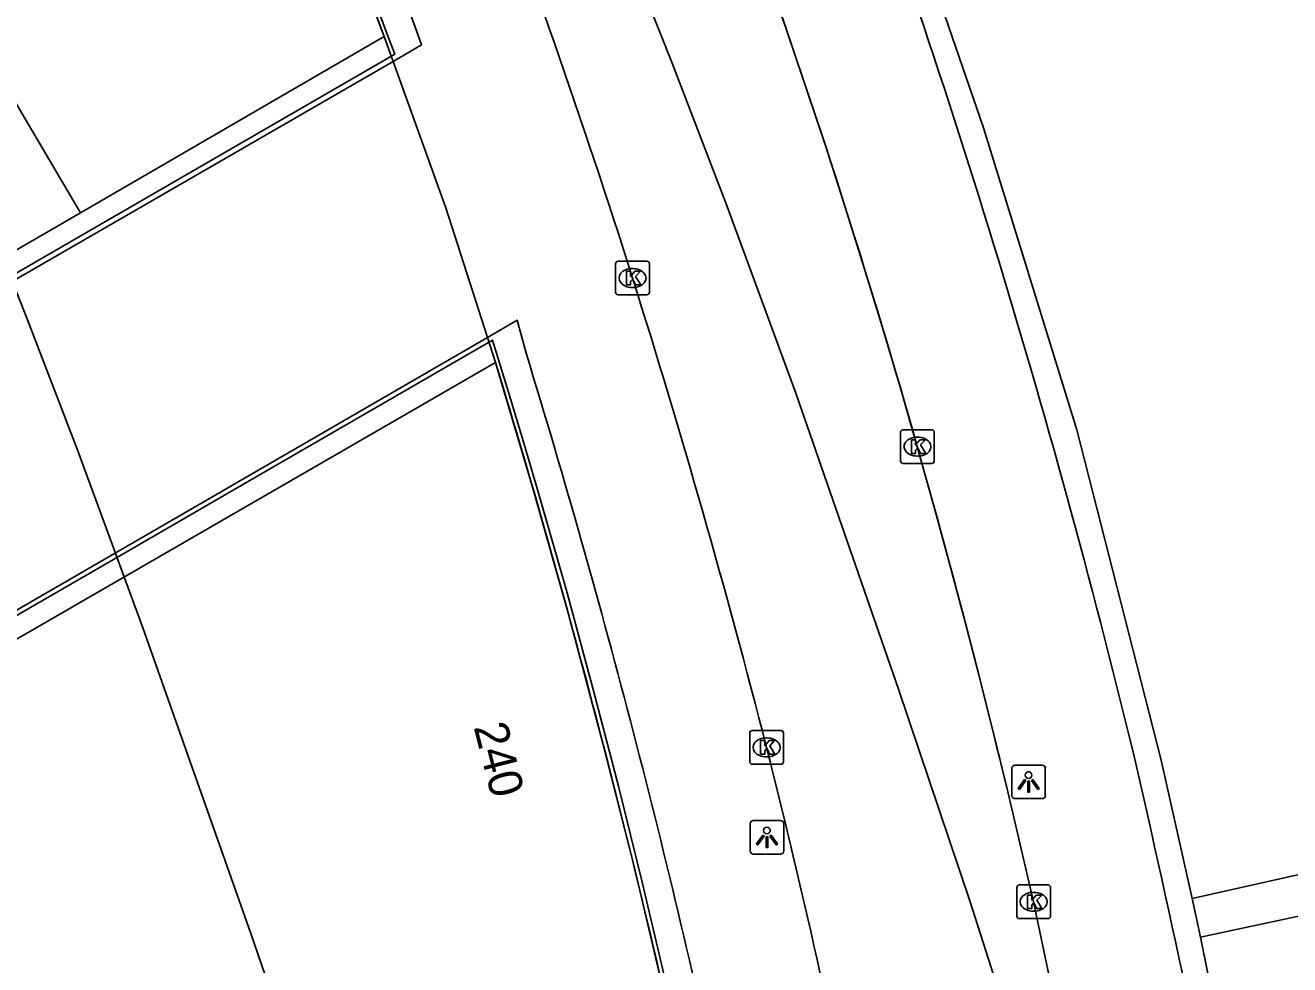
# Model space of a CAD drawing. Extents: x 155018 to 156648, y 383980 to 385733.
# Drawn here: x 156027.46 to 156064.97, y 384892.15 to 384920.02 of the extents above; entities that cross this region are included whole.
import ezdxf

# ---------------------------------------------------------------- set-up
doc = ezdxf.new("R2010")
doc.units = 0
for name, color, linetype in [('IMGEO_Dek', 7, 'Continuous'), ('IMGEO_Hek', 7, 'Continuous'), ('IMGEO_Kolk', 7, 'Continuous'), ('IMGEO_Lichtpunt', 7, 'Continuous'), ('IMGEO_Lijnafwatering', 7, 'Continuous'), ('IMGEO_OVBaan_gesloten', 7, 'Continuous'), ('IMGEO_Pand', 7, 'Continuous'), ('IMGEO_Pand_nummerreeks', 7, 'Continuous'), ('IMGEO_Pand_overbouw', 7, 'Continuous'), ('IMGEO_Parkeervlak_open', 7, 'Continuous'), ('IMGEO_Voetpad_gesloten', 7, 'Continuous'), ('IMGEO_Voetpad_op_trap', 7, 'Continuous'), ('IMGEO_Voetpad_open', 7, 'Continuous')]:
    doc.layers.add(name, color=color, linetype=linetype)

msp = doc.modelspace()

# ---------------------------------------------------------------- linework, layer by layer
at = {"layer": 'IMGEO_Dek'}
for points in [[(156068.116, 384859.746), (156067.041, 384867.895), (156066.062, 384873.898), (156064.757, 384880.912), (156062.331, 384892.966), (156062.08, 384894.114), (156061.157, 384898.221), (156058.656, 384908.023), (156055.886, 384916.978), (156051.936, 384928.479), (156048.02, 384938.183), (156047.794, 384938.745), (156047.79, 384938.857), (156046.063, 384942.673), (156044.343, 384946.44)], [(156027.709, 384944.118), (156028.763, 384941.944), (156029.793, 384939.759), (156030.8, 384937.563), (156031.783, 384935.357), (156032.743, 384933.14), (156033.68, 384930.916), (156034.6, 384928.685), (156035.502, 384926.446), (156036.386, 384924.2), (156037.253, 384921.947), (156038.102, 384919.688), (156039.932, 384914.604), (156041.169, 384910.762), (156041.409, 384910.017), (156042.517, 384906.291), (156043.573, 384902.55), (156044.577, 384898.794), (156045.528, 384895.025), (156046.426, 384891.242)]]:
    msp.add_lwpolyline(points, dxfattribs=at)
at = {"layer": 'IMGEO_Hek'}
for centre, radius, start, end in [((155804.106, 384836.212), 263.673, 13.559, 20.33305), ((155627.906, 384798.953), 443.726, 8.87476, 12.90185)]:
    msp.add_arc(centre, radius, start, end, dxfattribs=at)
at = {"layer": 'IMGEO_Kolk'}
for p, q in [((156044.973, 384912.099), (156044.973, 384912.951)), ((156045.048, 384913.025), (156045.9, 384913.025)), ((156045.461, 384912.805), (156045.486, 384912.805)), ((156045.974, 384912.951), (156045.974, 384912.099)), ((156045.484, 384912.245), (156045.459, 384912.245)), ((156045.9, 384912.025), (156045.048, 384912.025)), ((156053.428, 384907.096), (156053.428, 384907.948)), ((156053.503, 384908.022), (156054.355, 384908.022)), ((156054.429, 384907.948), (156054.429, 384907.096)), ((156053.916, 384907.802), (156053.941, 384907.802)), ((156053.939, 384907.242), (156053.914, 384907.242)), ((156054.355, 384907.022), (156053.503, 384907.022)), ((156048.953, 384898.173), (156048.953, 384899.025)), ((156049.028, 384899.099), (156049.88, 384899.099)), ((156049.954, 384899.025), (156049.954, 384898.173)), ((156049.441, 384898.879), (156049.466, 384898.879)), ((156049.464, 384898.319), (156049.439, 384898.319)), ((156049.88, 384898.099), (156049.028, 384898.099)), ((156056.878, 384893.592), (156056.878, 384894.444)), ((156056.953, 384894.518), (156057.805, 384894.518)), ((156057.879, 384894.444), (156057.879, 384893.592)), ((156057.366, 384894.298), (156057.391, 384894.298)), ((156057.389, 384893.738), (156057.364, 384893.738)), ((156057.805, 384893.518), (156056.953, 384893.518))]:
    msp.add_line(p, q, dxfattribs=at)
for points in [[(156044.973, 384912.099), (156044.973, 384912.951)], [(156045.048, 384913.025), (156045.9, 384913.025)], [(156045.974, 384912.951), (156045.974, 384912.099)], [(156045.294, 384912.725), (156045.417, 384912.725), (156045.417, 384912.574), (156045.547, 384912.725), (156045.711, 384912.725), (156045.565, 384912.574), (156045.718, 384912.325), (156045.566, 384912.325), (156045.481, 384912.489), (156045.417, 384912.422), (156045.417, 384912.325), (156045.294, 384912.325), (156045.294, 384912.725)], [(156045.9, 384912.025), (156045.048, 384912.025)], [(156053.428, 384907.096), (156053.428, 384907.948)], [(156053.503, 384908.022), (156054.355, 384908.022)], [(156054.429, 384907.948), (156054.429, 384907.096)], [(156053.749, 384907.722), (156053.872, 384907.722), (156053.872, 384907.571), (156054.002, 384907.722), (156054.166, 384907.722), (156054.02, 384907.571), (156054.173, 384907.322), (156054.021, 384907.322), (156053.936, 384907.486), (156053.872, 384907.419), (156053.872, 384907.322), (156053.749, 384907.322), (156053.749, 384907.722)], [(156054.355, 384907.022), (156053.503, 384907.022)], [(156048.953, 384898.173), (156048.953, 384899.025)], [(156049.028, 384899.099), (156049.88, 384899.099)], [(156049.954, 384899.025), (156049.954, 384898.173)], [(156049.274, 384898.799), (156049.397, 384898.799), (156049.397, 384898.648), (156049.527, 384898.799), (156049.691, 384898.799), (156049.545, 384898.648), (156049.698, 384898.399), (156049.546, 384898.399), (156049.461, 384898.563), (156049.397, 384898.496), (156049.397, 384898.399), (156049.274, 384898.399), (156049.274, 384898.799)], [(156049.88, 384898.099), (156049.028, 384898.099)], [(156056.878, 384893.592), (156056.878, 384894.444)], [(156056.953, 384894.518), (156057.805, 384894.518)], [(156057.879, 384894.444), (156057.879, 384893.592)], [(156057.199, 384894.218), (156057.322, 384894.218), (156057.322, 384894.067), (156057.452, 384894.218), (156057.616, 384894.218), (156057.47, 384894.067), (156057.623, 384893.818), (156057.471, 384893.818), (156057.386, 384893.982), (156057.322, 384893.915), (156057.322, 384893.818), (156057.199, 384893.818), (156057.199, 384894.218)], [(156057.805, 384893.518), (156056.953, 384893.518)]]:
    msp.add_lwpolyline(points, dxfattribs=at)
for centre, start, end in [((156045.05, 384912.949), 91.552, 178.448), ((156045.05, 384912.949), 91.552, 178.448), ((156045.898, 384912.949), 1.552, 88.448), ((156045.898, 384912.949), 1.552, 88.448), ((156045.05, 384912.101), 181.552, 268.448), ((156045.05, 384912.101), 181.552, 268.448), ((156045.898, 384912.101), 271.552, 358.448), ((156045.898, 384912.101), 271.552, 358.448), ((156053.505, 384907.946), 91.552, 178.448), ((156053.505, 384907.946), 91.552, 178.448), ((156054.353, 384907.946), 1.552, 88.448), ((156054.353, 384907.946), 1.552, 88.448), ((156053.505, 384907.098), 181.552, 268.448), ((156053.505, 384907.098), 181.552, 268.448), ((156054.353, 384907.098), 271.552, 358.448), ((156054.353, 384907.098), 271.552, 358.448), ((156049.03, 384899.023), 91.552, 178.448), ((156049.03, 384899.023), 91.552, 178.448), ((156049.878, 384899.023), 1.552, 88.448), ((156049.878, 384899.023), 1.552, 88.448), ((156049.03, 384898.175), 181.552, 268.448), ((156049.03, 384898.175), 181.552, 268.448), ((156049.878, 384898.175), 271.552, 358.448), ((156049.878, 384898.175), 271.552, 358.448), ((156056.955, 384894.442), 91.552, 178.448), ((156056.955, 384894.442), 91.552, 178.448), ((156057.803, 384894.442), 1.552, 88.448), ((156057.803, 384894.442), 1.552, 88.448), ((156056.955, 384893.594), 181.552, 268.448), ((156056.955, 384893.594), 181.552, 268.448), ((156057.803, 384893.594), 271.552, 358.448), ((156057.803, 384893.594), 271.552, 358.448)]:
    msp.add_arc(centre, 0.0765, start, end, dxfattribs=at)
for centre, major_axis, ratio, start_param, end_param in [((156045.46, 384912.525), (-0.387, 0.002), 0.722429, 4.712389, 7.853982), ((156045.485, 384912.525), (-0.39, 0.002), 0.717154, 1.570796, 4.712389), ((156053.915, 384907.522), (-0.387, 0.002), 0.722429, 4.712389, 7.853982), ((156053.94, 384907.522), (-0.39, 0.002), 0.717154, 1.570796, 4.712389), ((156049.44, 384898.599), (-0.387, 0.002), 0.722429, 4.712389, 7.853982), ((156049.465, 384898.599), (-0.39, 0.002), 0.717154, 1.570796, 4.712389), ((156057.365, 384894.018), (-0.387, 0.002), 0.722429, 4.712389, 7.853982), ((156057.39, 384894.018), (-0.39, 0.002), 0.717154, 1.570796, 4.712389)]:
    msp.add_ellipse(centre, major_axis=major_axis, ratio=ratio, start_param=start_param, end_param=end_param, dxfattribs=at)
at = {"layer": 'IMGEO_Lichtpunt'}
for p, q in [((156056.727, 384897.979), (156056.727, 384897.172)), ((156056.727, 384897.979), (156056.727, 384897.172)), ((156057.629, 384898.074), (156056.821, 384898.074)), ((156057.629, 384898.074), (156056.821, 384898.074)), ((156057.723, 384897.172), (156057.723, 384897.979)), ((156057.723, 384897.172), (156057.723, 384897.979)), ((156056.821, 384897.078), (156057.629, 384897.078)), ((156056.821, 384897.078), (156057.629, 384897.078)), ((156048.964, 384896.333), (156048.964, 384895.526)), ((156048.964, 384896.333), (156048.964, 384895.526)), ((156049.866, 384896.428), (156049.058, 384896.428)), ((156049.866, 384896.428), (156049.058, 384896.428)), ((156049.96, 384895.526), (156049.96, 384896.333)), ((156049.96, 384895.526), (156049.96, 384896.333)), ((156049.058, 384895.432), (156049.866, 384895.432)), ((156049.058, 384895.432), (156049.866, 384895.432))]:
    msp.add_line(p, q, dxfattribs=at)
for points in [[(156057.101, 384897.643), (156057.14, 384897.615), (156056.952, 384897.353), (156056.914, 384897.38), (156057.101, 384897.643)], [(156057.203, 384897.595), (156057.25, 384897.595), (156057.25, 384897.273), (156057.203, 384897.273), (156057.203, 384897.595)], [(156057.313, 384897.615), (156057.351, 384897.642), (156057.538, 384897.38), (156057.499, 384897.352), (156057.313, 384897.615)], [(156049.338, 384895.997), (156049.377, 384895.969), (156049.189, 384895.707), (156049.151, 384895.734), (156049.338, 384895.997)], [(156049.44, 384895.949), (156049.487, 384895.949), (156049.487, 384895.627), (156049.44, 384895.627), (156049.44, 384895.949)], [(156049.55, 384895.969), (156049.588, 384895.996), (156049.775, 384895.734), (156049.736, 384895.706), (156049.55, 384895.969)]]:
    msp.add_lwpolyline(points, dxfattribs=at)
for centre in [(156057.226, 384897.777), (156049.463, 384896.131)]:
    msp.add_circle(centre, 0.0994, dxfattribs=at)
for centre, start, end in [((156056.821, 384897.979), 90, 180), ((156056.821, 384897.979), 90, 180), ((156057.629, 384897.979), 0, 90), ((156057.629, 384897.979), 0, 90), ((156056.821, 384897.172), 180, 270), ((156056.821, 384897.172), 180, 270), ((156057.629, 384897.172), 270, 0), ((156057.629, 384897.172), 270, 360), ((156049.058, 384896.333), 90, 180), ((156049.058, 384896.333), 90, 180), ((156049.866, 384896.333), 0, 90), ((156049.866, 384896.333), 0, 90), ((156049.058, 384895.526), 180, 270), ((156049.058, 384895.526), 180, 270), ((156049.866, 384895.526), 270, 0), ((156049.866, 384895.526), 270, 360)]:
    msp.add_arc(centre, 0.0946, start, end, dxfattribs=at)
at = {"layer": 'IMGEO_Lijnafwatering'}
for points in [[(156027.883, 384913.07), (156038.418, 384919.164), (156038.205, 384919.727), (156038.105, 384919.996), (156038.004, 384920.266), (156037.903, 384920.535), (156037.097, 384922.66), (156036.276, 384924.779), (156035.44, 384926.892)], [(156010.178, 384902.83), (156024.932, 384911.364), (156027.883, 384913.07)], [(156045.059, 384897.444), (156044.311, 384900.321), (156043.53, 384903.189), (156042.715, 384906.047), (156042.259, 384907.596), (156041.793, 384909.141), (156041.318, 384910.683), (156033.931, 384906.41)], [(156033.931, 384906.41), (156030.071, 384904.178), (156014.633, 384895.249)], [(156037.593, 384881.157), (156047.505, 384886.874), (156047.372, 384887.505), (156047.238, 384888.135), (156047.102, 384888.765), (156046.454, 384891.666), (156045.773, 384894.559), (156045.059, 384897.444)]]:
    msp.add_lwpolyline(points, dxfattribs=at)
at = {"layer": 'IMGEO_OVBaan_gesloten'}
for points in [[(156049.419, 384921.673), (156050.032, 384919.92), (156050.631, 384918.162), (156051.216, 384916.399), (156051.786, 384914.631), (156052.342, 384912.859), (156052.884, 384911.082), (156053.411, 384909.301), (156053.924, 384907.516), (156054.394, 384905.839), (156054.854, 384904.159), (156055.301, 384902.476), (156055.738, 384900.79), (156056.163, 384899.101), (156056.577, 384897.409), (156056.979, 384895.715), (156057.37, 384894.018), (156058.869, 384886.937)], [(156057.37, 384894.018), (156058.869, 384886.937), (156060.496, 384878.537)]]:
    msp.add_lwpolyline(points, dxfattribs=at)
for centre, radius, start, end in [((155806.272, 384836.791), 250.906, 17.568, 20.93768), ((155806.272, 384836.791), 250.906, 17.568, 20.93768), ((155832.964, 384844.998), 229.634, 15.79822, 19.5057), ((155789.737, 384831.978), 268.122, 14.38694, 17.48212), ((155789.737, 384831.978), 268.122, 14.38694, 17.48212), ((155805.27, 384836.847), 258.501, 12.77748, 15.86559), ((155805.555, 384837.135), 251.521, 10.99889, 14.14425), ((155805.555, 384837.135), 251.521, 10.99889, 14.14425)]:
    msp.add_arc(centre, radius, start, end, dxfattribs=at)
at = {"layer": 'IMGEO_Pand'}
for points in [[(156029.096, 384914.462), (156021.332, 384927.645), (156017.667, 384933.972), (156014.565, 384939.327), (156002.887, 384932.567), (156009.646, 384920.869), (156017.206, 384907.579)], [(156029.096, 384914.462), (156038.102, 384919.688)], [(155996.821, 384884.308), (156002.181, 384887.356), (156003.544, 384885.006), (156008.617, 384887.934), (156007.252, 384890.298), (156015.467, 384895.04), (156019.378, 384897.297), (156041.409, 384910.017)]]:
    msp.add_lwpolyline(points, dxfattribs=at)
for centre, radius, start, end in [((155751.344, 384813.243), 305.877, 20.36501, 23.07763), ((155775.793, 384828.981), 277.703, 12.1539, 16.96628)]:
    msp.add_arc(centre, radius, start, end, dxfattribs=at)
at = {"layer": 'IMGEO_Pand_overbouw'}
for points in [[(156065.601, 384858.12), (156061.663, 384873.134), (156060.081, 384879.164), (156057.992, 384886.194), (156055.482, 384894.048), (156053.363, 384900.328), (156050.321, 384909.105), (156048.279, 384914.644), (156046.647, 384918.9), (156044.351, 384924.676), (156043.087, 384927.641), (156041.379, 384931.534), (156039.688, 384935.316), (156037.638, 384939.699), (156032.938, 384949.258)], [(156010.865, 384946.812), (156014.639, 384939.822), (156019.077, 384930.797), (156020.968, 384926.754), (156022.558, 384923.198), (156024.194, 384919.469), (156025.317, 384916.836), (156027.472, 384911.414), (156029.011, 384907.398), (156030.938, 384902.172), (156034.148, 384893.08), (156035.96, 384887.818), (156037.993, 384881.487), (156039.75, 384875.68), (156040.562, 384872.8), (156042.005, 384867.554), (156043.013, 384863.814), (156044.557, 384857.338)]]:
    msp.add_lwpolyline(points, dxfattribs=at)
msp.add_lwpolyline([(156021.332, 384927.645), (156009.646, 384920.869), (156017.206, 384907.579), (156029.096, 384914.462)], close=True, dxfattribs=at)
at = {"layer": 'IMGEO_Parkeervlak_open'}
msp.add_arc((156414.727, 385106.453), 394.545, 207.33972, 209.36688, dxfattribs=at)
at = {"layer": 'IMGEO_Voetpad_gesloten'}
for points in [[(156068.116, 384859.746), (156067.041, 384867.895), (156066.062, 384873.898), (156064.757, 384880.912), (156062.331, 384892.966), (156062.08, 384894.114), (156061.157, 384898.221), (156058.656, 384908.023), (156055.886, 384916.978), (156051.936, 384928.479), (156048.02, 384938.183), (156047.794, 384938.745), (156047.79, 384938.857), (156046.063, 384942.673), (156044.343, 384946.44)], [(156048.02, 384938.183), (156051.936, 384928.479), (156055.886, 384916.978), (156058.656, 384908.023), (156061.157, 384898.221), (156062.08, 384894.114)], [(156038.367, 384918.952), (156039.21, 384919.439), (156039.002, 384920.023)], [(156038.102, 384919.688), (156039.932, 384914.604), (156041.169, 384910.762), (156041.409, 384910.017)], [(156038.367, 384918.952), (156038.102, 384919.688)], [(156041.169, 384910.762), (156019.469, 384898.196), (156015.169, 384905.56), (156038.367, 384918.952)], [(156038.367, 384918.952), (156039.932, 384914.604), (156041.169, 384910.762)], [(156042.318, 384910.295), (156042.048, 384911.271), (156041.169, 384910.762)], [(156041.169, 384910.762), (156041.409, 384910.017)], [(156062.331, 384892.966), (156062.08, 384894.114)], [(156062.331, 384892.966), (156064.757, 384880.912), (156066.062, 384873.898), (156067.041, 384867.895), (156068.116, 384859.746), (156069.485, 384845.924)]]:
    msp.add_lwpolyline(points, dxfattribs=at)
for centre, radius, start, end in [((155742.612, 384809.738), 316.243, 20.41, 23.47464), ((155751.344, 384813.243), 305.877, 20.36501, 23.07763), ((155782.511, 384830.732), 271.716, 12.09103, 17.02669), ((155775.793, 384828.981), 277.703, 12.1539, 16.96628)]:
    msp.add_arc(centre, radius, start, end, dxfattribs=at)
at = {"layer": 'IMGEO_Voetpad_op_trap'}
msp.add_lwpolyline([(156062.08, 384894.114), (156067.946, 384895.427), (156068.244, 384894.235), (156062.331, 384892.966)], dxfattribs=at)
at = {"layer": 'IMGEO_Voetpad_open'}
msp.add_lwpolyline([(156017.206, 384907.579), (156029.096, 384914.462)], dxfattribs=at)

# ---------------------------------------------------------------- texts
at = {"layer": 'IMGEO_Pand_nummerreeks'}
msp.add_text('240', height=1, rotation=284.3493, dxfattribs=at).set_placement((156040.756, 384899.208))

doc.saveas('drawing.dxf')
